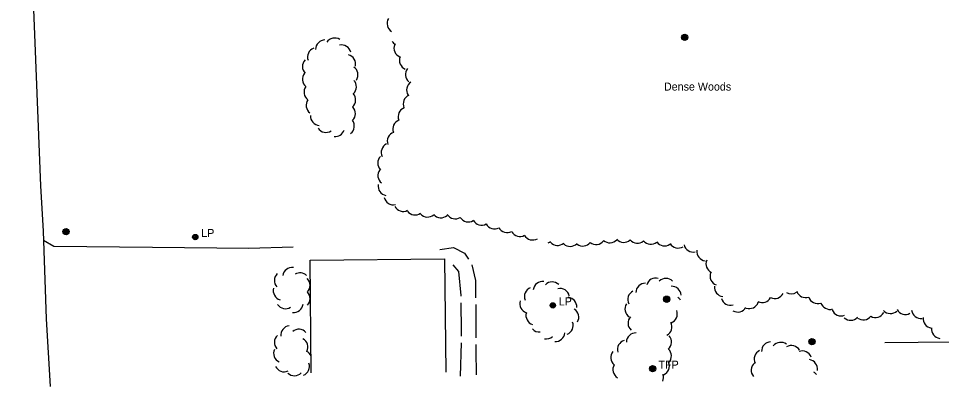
# Model space of a CAD drawing. Extents: x 2402803 to 2427059, y 6985292 to 6997652.
# Drawn here: x 2405045 to 2405598, y 6990700 to 6990921 of the extents above; entities that cross this region are included whole.
import ezdxf

# ---------------------------------------------------------------- set-up
doc = ezdxf.new("R2010")
doc.units = 0
for name, color, linetype in [('p_road - paved curb', 7, 'Continuous'), ('p_road dirt road', 7, 'Continuous'), ('p_structure building', 7, 'Continuous'), ('p_structure fence', 7, 'Continuous'), ('p_utility manhole', 7, 'Continuous'), ('p_veg woods', 7, 'Continuous')]:
    doc.layers.add(name, color=color, linetype=linetype)

msp = doc.modelspace()

# ---------------------------------------------------------------- linework, layer by layer
at = {"layer": 'p_road - paved curb'}
for points in [[(2405045.62, 6991222.63), (2405045.14, 6991217.72), (2405043.03, 6991193.96), (2405043.43, 6991161.69), (2405045.69, 6991110.27), (2405047.05, 6991066.72), (2405049.77, 6991014.45), (2405051.88, 6990971.45), (2405054.52, 6990906.36), (2405058, 6990820.6), (2405059.43, 6990793.39), (2405061.36, 6990740.77), (2405063.75, 6990700.28)], [(2405059.63, 6990788.02), (2405065.98, 6990784.5), (2405125, 6990783.73), (2405182.84, 6990783.23), (2405209.42, 6990784.03)]]:
    msp.add_lwpolyline(points, dxfattribs=at)
at = {"layer": 'p_road dirt road'}
msp.add_line((2405310.06, 6990726.53), (2405309.64, 6990706.53), dxfattribs=at)
for points in [[(2405297.43, 6990782.47), (2405305.62, 6990783.54), (2405312.13, 6990780.25), (2405314.64, 6990776.59)], [(2405305.18, 6990773.16), (2405308.63, 6990769.23), (2405309.98, 6990754.81), (2405309.98, 6990754.52)], [(2405316.62, 6990773.16), (2405318.7, 6990763.84), (2405318.81, 6990753.4)], [(2405310.03, 6990750.52), (2405310.22, 6990733.84), (2405310.15, 6990730.53)], [(2405318.86, 6990749.4), (2405318.91, 6990744.68), (2405318.93, 6990729.4)], [(2405318.94, 6990725.4), (2405318.94, 6990722.03), (2405319.1, 6990707.39)]]:
    msp.add_lwpolyline(points, dxfattribs=at)
at = {"layer": 'p_structure building'}
msp.add_lwpolyline([(2405220.15, 6990708.58), (2405219.58, 6990775.99), (2405300.2, 6990776.81), (2405300.99, 6990708.9)], dxfattribs=at)
at = {"layer": 'p_structure fence'}
msp.add_line((2405564.19, 6990726.6), (2405604.14, 6990727.17), dxfattribs=at)
at = {"layer": 'p_utility manhole'}
for centre, radius in [((2405444.19, 6990909.63), 1.9), ((2405444.19, 6990909.63), 1.44), ((2405444.19, 6990909.63), 0.973), ((2405444.19, 6990909.63), 0.539), ((2405444.19, 6990909.63), 0.192), ((2405073.25, 6990793.11), 1.9), ((2405073.25, 6990793.11), 1.44), ((2405073.25, 6990793.11), 0.973), ((2405073.25, 6990793.11), 0.539), ((2405073.25, 6990793.11), 0.192), ((2405150.75, 6990789.89), 1.6), ((2405150.75, 6990789.89), 1.3), ((2405150.75, 6990789.89), 1), ((2405150.75, 6990789.89), 0.539), ((2405150.75, 6990789.89), 0.192), ((2405433.4, 6990752.63), 1.9), ((2405433.4, 6990752.63), 1.44), ((2405433.4, 6990752.63), 0.973), ((2405433.4, 6990752.63), 0.539), ((2405433.4, 6990752.63), 0.192), ((2405365.09, 6990748.91), 1.6), ((2405365.09, 6990748.91), 1.3), ((2405365.09, 6990748.91), 1), ((2405365.09, 6990748.91), 0.539), ((2405365.09, 6990748.91), 0.192), ((2405520.48, 6990727.17), 1.9), ((2405520.48, 6990727.17), 1.44), ((2405520.48, 6990727.17), 0.973), ((2405520.48, 6990727.17), 0.539), ((2405520.48, 6990727.17), 0.192), ((2405424.92, 6990710.98), 1.9), ((2405424.92, 6990710.98), 1.44), ((2405424.92, 6990710.98), 0.973), ((2405424.92, 6990710.98), 0.539), ((2405424.92, 6990710.98), 0.192)]:
    msp.add_circle(centre, radius, dxfattribs=at)
at = {"layer": 'p_veg woods'}
for centre, start, end in [((2405271.37, 6990917.94), 149.1541, 239.1541), ((2405228.52, 6990902.39), 90.2412, 180.2412), ((2405234.3, 6990903.54), 57.2372, 147.2372), ((2405273.4, 6990910.41), 214.7935, 242.0932), ((2405223.65, 6990897.75), 109.8024, 199.8024), ((2405238.47, 6990899.36), 13.2875, 103.2875), ((2405275.52, 6990903.12), 158.0352, 248.0352), ((2405220.62, 6990892.15), 136.1121, 226.1121), ((2405241.22, 6990893.63), 346.0863, 76.0863), ((2405278.77, 6990895.79), 157.7854, 247.7854), ((2405242.6, 6990887.08), 326.6324, 56.6324), ((2405282.43, 6990887.28), 140.8547, 230.8547), ((2405220.62, 6990884.5), 141.272, 231.272), ((2405221.59, 6990876.74), 143.8373, 233.8373), ((2405241.7, 6990879.94), 313.3168, 43.3168), ((2405283.07, 6990878.04), 123.0196, 213.0196), ((2405241.23, 6990872.05), 311.9959, 41.9959), ((2405281.04, 6990869.62), 113.6275, 203.6275), ((2405222.82, 6990868.84), 143.8373, 233.8373), ((2405241.12, 6990863.88), 314.4774, 44.4774), ((2405225.38, 6990862.46), 177.5384, 266.9335), ((2405278.02, 6990862.07), 111.6524, 201.6524), ((2405240.43, 6990856.41), 307.4267, 37.4267), ((2405274.84, 6990854.69), 111.1546, 201.1546), ((2405229.02, 6990858.27), 213.7396, 303.7396), ((2405234.55, 6990855.76), 264.8474, 341.9356), ((2405271.49, 6990847.25), 108.949, 198.949), ((2405267.87, 6990840.71), 117.0762, 207.0762), ((2405265.75, 6990834.28), 135.4898, 225.4898), ((2405265.84, 6990826.78), 142.6791, 232.6791), ((2405266.03, 6990820.34), 169.5544, 259.5544), ((2405269.57, 6990814.82), 191.9228, 281.9228), ((2405275.31, 6990810.9), 207.8407, 297.8407), ((2405282.46, 6990808.77), 215.743, 305.743), ((2405289.99, 6990807.52), 221.0581, 311.0581), ((2405297.99, 6990807.07), 220.8097, 310.8097), ((2405306.62, 6990806.44), 211.6832, 301.6832), ((2405314.44, 6990804.59), 211.2832, 301.2831), ((2405322.36, 6990802.68), 209.107, 299.107), ((2405330.09, 6990800.45), 208.4333, 298.4333), ((2405337.76, 6990798.17), 208.4217, 298.4217), ((2405345.34, 6990795.88), 209.6815, 299.6815), ((2405352.98, 6990793.76), 210.7052, 300.7052), ((2405360.41, 6990791.77), 290.56, 305.2199), ((2405367.89, 6990790.52), 221.1739, 311.1739), ((2405375.48, 6990789.91), 226.8499, 316.8499), ((2405383.14, 6990790.15), 231.7619, 321.7619), ((2405391.08, 6990791.09), 231.7619, 321.7619), ((2405399.31, 6990792.07), 227.7287, 317.7287), ((2405407.73, 6990792.33), 221.7476, 311.7476), ((2405415.85, 6990791.88), 219.7271, 309.7271), ((2405423.93, 6990791.18), 218.1866, 308.1866), ((2405432.07, 6990790.23), 215.389, 305.389), ((2405440.25, 6990788.91), 211.3537, 301.3537), ((2405449.3, 6990786.53), 192.5975, 282.5975), ((2405457.1, 6990781.2), 172.5041, 262.5041), ((2405462.57, 6990773.85), 156.4074, 246.4074), ((2405203.78, 6990763.85), 133.1594, 223.1594), ((2405208.72, 6990765.97), 81.6558, 171.6558), ((2405213.53, 6990762.77), 45.9534, 120.6659), ((2405465.03, 6990766.49), 159.9688, 249.9688), ((2405213.93, 6990760.92), 315.769, 45.769), ((2405359, 6990757.61), 82.6606, 172.6606), ((2405364.69, 6990757.32), 45.3615, 135.3615), ((2405426.84, 6990759.65), 74.5327, 164.5327), ((2405432.9, 6990759.47), 44.5498, 134.5498), ((2405203.14, 6990757.71), 163.5242, 253.5242), ((2405213.95, 6990753), 314.6385, 44.6385), ((2405353.71, 6990754.23), 111.7485, 201.7485), ((2405369.47, 6990753.39), 13.0798, 103.0798), ((2405415.67, 6990752.44), 116.841, 206.841), ((2405420.52, 6990756.51), 89.2994, 179.2994), ((2405436.39, 6990754.74), 2.8403, 92.8403), ((2405467.61, 6990759.87), 173.9085, 263.9085), ((2405516.74, 6990759.2), 198.7467, 288.7467), ((2405350.94, 6990749.92), 162.5252, 252.5252), ((2405373.8, 6990748.12), 355.1358, 85.1358), ((2405437.01, 6990748.92), 34.1585, 56.3302), ((2405471.57, 6990754.67), 196.8019, 286.8019), ((2405490.62, 6990756.23), 243.3864, 333.3864), ((2405498.27, 6990758.71), 242.7035, 332.7035), ((2405508.11, 6990761.56), 239.8679, 302.195), ((2405523.9, 6990755.67), 198.9542, 288.9542), ((2405204.77, 6990752.57), 212.7776, 302.7776), ((2405209.73, 6990750.36), 262.81, 352.81), ((2405375.03, 6990741.85), 329.2827, 59.2827), ((2405414, 6990746.75), 147.151, 237.151), ((2405434.08, 6990743.81), 290.5916, 20.5916), ((2405475.99, 6990750.58), 239.5856, 329.5856), ((2405482.93, 6990752.66), 250.2591, 340.2591), ((2405531.24, 6990752.16), 196.9677, 286.9677), ((2405537.85, 6990748.29), 202.1213, 292.1213), ((2405567.53, 6990749.67), 222.8489, 312.8489), ((2405576.51, 6990749.11), 208.8448, 298.8448), ((2405585.84, 6990746.74), 187.6503, 277.6503), ((2405354.64, 6990742.83), 162.5252, 252.5252), ((2405415.87, 6990738.25), 137.152, 227.152), ((2405543.66, 6990745.62), 227.2131, 317.2131), ((2405551.23, 6990745.87), 233.367, 323.367), ((2405558.55, 6990747.32), 240.7827, 330.7827), ((2405592.76, 6990740.94), 172.8048, 262.8048), ((2405207.66, 6990731.1), 97.3618, 187.3618), ((2405356.99, 6990738.62), 222.6873, 275.3923), ((2405371.7, 6990736.92), 290.4927, 20.4927), ((2405430.8, 6990736.02), 297.6943, 27.6943), ((2405597.85, 6990734.75), 172.5955, 262.5955), ((2405203.79, 6990726.72), 132.666, 222.666), ((2405212.84, 6990728.99), 41.1643, 131.1643), ((2405361.15, 6990734.45), 259.0894, 311.2806), ((2405366.69, 6990732.93), 265.4865, 355.4865), ((2405414.87, 6990726.79), 88.2323, 178.2323), ((2405430.61, 6990727.01), 310.8672, 40.8672), ((2405212.64, 6990723.95), 332.3176, 62.3176), ((2405409.51, 6990722.49), 106.0016, 196.0016), ((2405495.92, 6990721.44), 92.3147, 182.3147), ((2405501.78, 6990721.13), 52.2015, 142.2015), ((2405508.19, 6990719.19), 31.2633, 121.2633), ((2405203.33, 6990720.18), 155.0775, 245.0775), ((2405215, 6990716.31), 25.0577, 62.1852), ((2405405.51, 6990717.77), 141.3588, 231.3588), ((2405430.58, 6990718.6), 316.9362, 46.9362), ((2405491.5, 6990716.69), 115.1843, 205.1843), ((2405514.7, 6990715.97), 20.1718, 110.1718), ((2405213.54, 6990712.29), 290.7416, 20.7416), ((2405406.77, 6990710.41), 148.861, 238.861), ((2405429.33, 6990712.58), 293.1812, 23.1812), ((2405489.68, 6990710.04), 130.4914, 220.4914), ((2405518.15, 6990710.82), 351.5108, 81.5108), ((2405204, 6990714.74), 204.6883, 294.6883), ((2405210.21, 6990712.41), 225.7062, 315.7062), ((2405425.82, 6990705.65), 337.1249, 19.8042), ((2405518.62, 6990704.17), 37.0313, 57.5288)]:
    msp.add_arc(centre, 5.65, start, end, dxfattribs=at)

# ---------------------------------------------------------------- texts
at = {"layer": 'p_utility manhole'}
for s, p in [('  LP', (2405150.75, 6990789.89)), ('  LP', (2405365.09, 6990748.91)), ('  TFP', (2405424.92, 6990710.98))]:
    msp.add_text(s, height=4.8, dxfattribs=at).set_placement(p)
at = {"layer": 'p_veg woods'}
msp.add_text('Dense Woods', height=4.8, dxfattribs=at).set_placement((2405431.74, 6990877.67))

doc.saveas('drawing.dxf')
